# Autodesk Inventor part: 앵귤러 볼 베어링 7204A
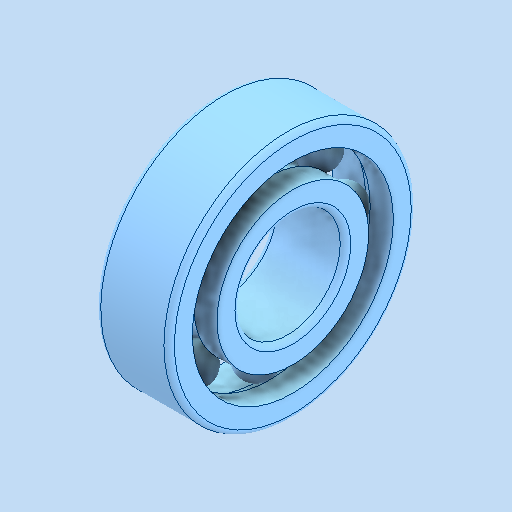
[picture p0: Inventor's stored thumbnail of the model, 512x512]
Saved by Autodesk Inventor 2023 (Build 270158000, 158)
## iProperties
Created: 2024-11
Part Number: 앵귤러 볼 베어링 7204A
Material: 강철, 연강
Description: 앵귤러 콘택트 볼 베어링
Document SubType Name: Modeling
Designer: asung
Density: 7.85 g/cm^3
Appearance: 기본값
Author: jhkim
Sending System: Autodesk Inventor 2025
Preprocessor: ST-DEVELOPER v20
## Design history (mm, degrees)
node "앵귤러 볼 제어링 7204A1"
node "솔리드1"
node "솔리드2"
node "솔리드3"
node "솔리드4"
node "솔리드5"
node "솔리드6"
node "솔리드7"
node "솔리드8"
node "솔리드9"
node "솔리드10"
body "Solid1"
node "Solid1:1"
node "Solid1:2"
node "Solid1:3"
node "Solid1:4"
node "Solid1:5"
node "Solid1:6"
node "Solid1:7"
node "Solid1:8"
node "Solid1:9"
